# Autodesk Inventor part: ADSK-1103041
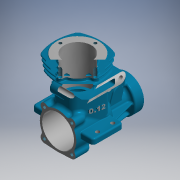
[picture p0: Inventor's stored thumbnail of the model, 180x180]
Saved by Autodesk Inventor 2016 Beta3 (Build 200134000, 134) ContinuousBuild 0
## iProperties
Shininess: 11.0
Length Units: 11269
Angle Units: 11279
Time Units: 11290
Mass Units: 11286
Length Display Precision: 2
Angle Display Precision: 2
Compacted: True
Created: 2000-07
Part Number: ADSK-1103041
Document SubType Name: Modeling
Material: Cast Steel
Description: ENGINE CASE - SIDE
Mass: 109.721 g
Surface Area: 158.984 cm^2
Volume: 13.9772 cm^3
Density: 7.85 g/cm^3
Appearance: Sky Blue Dark
Density: 0.0
Volumn: 0.0
Area: 0.0
PropertySet Name: Model Information
Control State: 0
Master: False
Checked Out: False
Author: Autodesk, Inc.
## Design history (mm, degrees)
node "Extrusion1" dims "d2" = 3.5, "d3" = 0
  sketch "Sketch2"
    geometry: L1 (-28.715, -16.977)-(11.285, -16.977); L2 (11.285, -16.977)-(11.285, 3.023); L3 (11.285, 3.023)-(-28.715, 3.023); L4 (-28.715, 3.023)-(-28.715, -16.977)
    constraints: 8 end point, 2 parallel, 1 horizontal, 1 perpendicular
    dimensions: "d0" = 40 distance of L2.end L3.end; "d1" = 20 distance of L3.end L1.start
workplane "Work Plane1"
workplane "Work Plane2"
node "Extrusion2" dims "d6" = 3.5, "d7" = 0
  sketch "Sketch3"
    geometry: L1 (20, -16.8)-(20, 16.8) reference; L2 (0, 0)-(40, 0) reference; C1 r 12 at (20, 0)
    constraints: 1 centre point, 1 midpoint
    dimensions: "d5" = 24 diameter of C1
node "Extrusion3" dims "d13" = 25, "d14" = 0
  sketch "Sketch4"
    geometry: L1 (-20.715, 3.023)-(3.285, 3.023); L2 (-2.715, -16.977)-(-14.715, -16.977); L3 (-8.715, -21.506)-(-8.715, 7.111) reference; L4 (-28.715, -16.977)-(-20.715, -16.977) reference; A1 r 36.333 centre (-33.049, 3.023) between (-2.715, -16.977) and (3.285, 3.023); A2 r 36.333 centre (15.618, 3.023) between (-20.715, 3.023) and (-14.715, -16.977)
    constraints: 4 end point, 4 point on circle, 2 centre point, 2 point on line, 1 collinear, 1 horizontal
    dimensions: "d8" = 24 distance of L1.start L1.end; "d9" = 12 distance of L2.start L2.end; "d10" = 6 distance from line of L3 L2.start (= 0.5 x d9); "d11" = 12 distance from line of L1.end L3 (= 0.5 x d8); "d12" = 20 distance between parallel lines of L2 L1
node "Extrusion4" dims "d15" = 2.5, "d16" = -15 deg
  sketch "Sketch5"
    geometry: A1 r 12 centre (-20, 3.5) between (-8, 3.5) and (-32, 3.5) reference; 1 further point
    constraints: 1 coincident, 1 horizontal alignment, 2 other
node "Extrusion5" dims "d18" = 14, "d19" = 0
  sketch "Sketch6"
    geometry: C1 r 11.33 at (0, 0) reference; C2 r 7.5 at (0, 0)
    constraints: 1 centre point, 1 coincident
    dimensions: "d17" = 15 diameter of C2
node "Extrusion6" dims "d21" = 6, "d22" = 0
  sketch "Sketch7"
    geometry: C1 r 7.5 at (0, 0) reference; C2 r 11 at (0, 0)
    constraints: 1 centre point, 1 coincident
    dimensions: "d20" = 22 diameter of C2
node "Extrusion7" dims "d24" = 1, "d25" = 0
  sketch "Sketch9"
    geometry: L1 (20.715, 3.023)-(28.715, 3.023) reference; L2 (20.715, 3.023)-(8.217, 3.023); L3 (8.217, 3.023)-(8.217, 19.523); L4 (8.217, 19.523)-(19.715, 19.523); L5 (18.215, 19.523)-(22.637, 3.023); L6 (19.715, 19.523)-(19.715, 25.523) reference; L7 (20.715, 3.023)-(20.045, 5.523) reference
    constraints: 8 end point, 2 parallel, 2 point on line, 1 collinear, 1 perpendicular
    dimensions: "d23" = 1.5 distance from line of L5.start L6
node "Mirror1"
node "Revolution1" dims "d28" = 90 deg
  sketch "Sketch10"
    geometry: L1 (-20, -3.5)-(0, -3.5) reference; L2 (-21.176, 0.363)-(-25.964, 13.518); L3 (-22.5, -2.5)-(-22.5, 7.83) reference; L4 (-22.5, 4)-(-36.5, 4) reference; L5 (-25.964, 13.518)-(-32.307, 11.21); L6 (-42.5, -14.5)-(-42.5, 7.5) reference; L7 (-32.307, 11.21)-(-27.519, -1.946); L8 (-27.519, -1.946)-(-21.176, 0.363)
    constraints: 8 end point, 2 perpendicular, 2 point on line, 1 parallel
    dimensions: "d26" = 70 deg angle of L1 L2; "d27" = 13.5 diameter of L2 L7; "d231" = 14 distance of L2.start L2.end
node "Extrusion9" dims "d35" = 1, "d36" = 0
  sketch "Sketch12"
    geometry: L1 (-26.964, 12.518)-(-19, 12.518); L2 (-19, 12.518)-(-19, 3); L3 (-19, 3)-(-26.964, 3); L4 (-26.964, 3)-(-26.964, 12.518); L5 (-25.964, 13.518)-(-22.5, 4) reference; L6 (-22.5, -2.5)-(-22.5, 7.83) reference; L7 (-20, 0)-(-20, 25) reference
    constraints: 8 end point, 2 parallel, 1 horizontal, 1 perpendicular
    dimensions: "d31" = 1 distance between parallel lines of L7 L2; "d32" = 1 distance from line of L5.start L4; "d33" = 1 distance from line of L5.end L3; "d34" = 1 horizontal distance of L5.start L1.start
workplane "Work Plane3"
  workaxis "Work Axis1"
node "Extrusion10" dims "d40" = 1, "d41" = 0
  sketch "Sketch13"
    geometry: L1 (-23, -12)-(-25.5, -11.33) reference; L2 (-25.5, -11.33)-(-25.5, 8.012) reference; L3 (-39.5, -11)-(-39.5, 11) reference; L4 (-25.5, -7.5)-(-39.5, -7.5) reference; L5 (-23, -12)-(-39.5, -10); L6 (-39.5, -6.5)-(-23, -6.5); L7 (-23, -6.5)-(-23, -12); 3 further points
    constraints: 6 end point, 2 point on line, 1 parallel, 1 perpendicular
    dimensions: "d38" = 1 distance of L3.start L5.end; "d39" = 1 distance between parallel lines of L4 L6
node "Circular Pattern1" dims "d42" = 30, "d44" = 45 deg
workaxis "Work Axis2"
workplane "Work Plane4"
workplane "Work Plane5"
workpoint "Work Point1"
node "Extrusion11" dims "d47" = 1, "d48" = 0
  sketch "Sketch14"
    geometry: L1 (2.217, 13.646)-(2.581, 12.646) reference; L2 (-3.407, -0.873)-(4.042, -0.873); L3 (-13.419, 36.867)-(12.256, -33.673) reference; L4 (4.042, -0.873)-(1.423, 6.324); L5 (-5.155, 3.93)-(-3.407, -0.873); A1 r 3.5 centre (-1.866, 5.127) between (1.423, 6.324) and (-5.155, 3.93); 1 further point
    constraints: 6 end point, 2 parallel, 2 point on circle, 2 tangent, 1 centre point, 1 horizontal, 1 point on line
    dimensions: "d45" = 3.5 radius of A1; "d46" = 6 distance from line of A1.centre L2; "d232" = 1 distance from line of point (5.681, 0.127) L2
node "Extrusion12" dims "d54" = 8, "d55" = 0
  sketch "Sketch15"
    geometry: L1 (-9, 9)-(9, 9); L2 (9, 9)-(9, -9); L3 (9, -9)-(-9, -9); L4 (-9, -9)-(-9, 9); C1 r 12 at (0, 0) reference; C2 r 2.5 at (-9, 9); C3 r 2.5 at (9, 9); C4 r 2.5 at (9, -9); C5 r 2.5 at (-9, -9)
    constraints: 8 end point, 4 centre point, 4 coincident, 3 equal radius, 2 parallel, 2 perpendicular, 1 horizontal
    dimensions: "d50" = 18 distance of L2.end L3.end; "d51" = 9 distance from line of C1.centre L4 (= 0.5 x d50); "d52" = 9 distance from line of C1.centre L3 (= d51); "d53" = 5 diameter of C3
node "Extrusion13" dims "d56" = 8, "d57" = 0
  sketch "Sketch16"
    geometry: L1 (10.857, -11.496)-(19.314, -11.98); L2 (29.143, -11.496)-(20.686, -11.98); A1 r 2.5 centre (11, -9) between (10.039, -6.692) and (13.308, -9.961) reference; A2 r 12 centre (20, 0) between (13.308, -9.961) and (26.692, -9.961) reference; A3 r 2.5 centre (29, -9) between (26.692, -9.961) and (29.961, -6.692) reference
    constraints: 4 end point, 4 point on circle, 4 tangent
node "Fillet1" dims "d58" = 2.5
node "Fillet2" dims "d59" = 2
node "Fillet3" dims "d60" = 5
node "Fillet4" dims "d61" = 3
node "Fillet5" dims "d62" = 2
node "Revolution2" dims "d63" = 180 deg
  sketch "Sketch17"
    geometry: L1 (0.686, 11.98)-(9.143, 11.496) reference; L2 (9.143, 11.496)-(0.686, 11.98); L3 (0.686, 11.98)-(0.543, 9.484); L4 (0.543, 9.484)-(9, 9); L5 (9, 9)-(9.143, 11.496); L6 (9, 9)-(11.496, 8.857); A1 r 12 centre (0, 0) between (9.961, 6.692) and (0.686, 11.98) reference; A2 r 2.5 centre (9, 9) between (9.961, 6.692) and (9.143, 11.496) reference
    constraints: 10 end point, 3 equal length, 2 perpendicular, 2 tangent, 1 point on circle, 1 point on line
node "Mirror2"
node "Fillet6" dims "d64" = 2.5
node "Fillet7" dims "d65" = 2
node "Fillet8" dims "d66" = 3.5
node "Fillet9" dims "d67" = 2
node "Fillet10" dims "d68" = 1
node "Fillet11" dims "d69" = 1
node "Fillet12" dims "d70" = 0.5
node "Fillet13" dims "d71" = 0.45
node "Fillet15" dims "d73" = 1
node "Fillet16" dims "d74" = 0.5
node "Fillet17" dims "d75" = 2
node "Fillet18" dims "d76" = 1
node "Fillet19" dims "d77" = 0.5
node "Fillet20" dims "d78" = 0.5
node "Fillet21" dims "d79" = 1
node "Fillet22" dims "d80" = 0.5
node "Fillet23" dims "d81" = 0.5
node "Fillet24" dims "d82" = 1
node "Fillet25" dims "d83" = 0.5
node "Extrusion14" dims "d84" = 9, "d85" = 0
  sketch "Sketch18"
    geometry: L1 (-17.028, 3.023)-(-0.402, 3.023) reference; L2 (-8.715, -24.577)-(-8.715, 7.623) reference; C1 r 10.018 at (-8.715, -6.996); A1 r 36.333 centre (15.618, 3.023) between (-20.508, -0.85) and (-16.281, -14.371) reference
    constraints: 2 tangent, 1 centre point, 1 point on line
node "Extrusion15" dims "d90" = 1, "d91" = 0
  sketch "Sketch19"
    geometry: L1 (5.035, 6.754)-(-22.465, 6.754); L2 (-22.465, 6.754)-(-22.465, -20.746); L3 (-22.465, -20.746)-(5.035, -20.746); L4 (5.035, -20.746)-(5.035, 6.754); A1 r 10.018 centre (-8.715, -6.996) between (0.549, -10.81) and (-8.715, 3.023) reference; A2 r 27.5 centre (-22.465, -6.996) between (2.599, -18.31) and (2.599, 4.319); A3 r 27.5 centre (5.035, -6.996) between (-20.03, 4.319) and (-20.03, -18.31); A4 r 27.5 centre (-8.715, 6.754) between (-20.03, -18.31) and (2.599, -18.31); A5 r 27.5 centre (-8.715, -20.746) between (2.599, 4.319) and (-20.03, 4.319); A6 r 29.032 centre (-8.715, -20.746) between (-22.465, 4.823) and (-23.458, 4.264)
    constraints: 12 point on circle, 8 end point, 5 centre point, 3 midpoint, 3 tangent, 2 parallel, 2 perpendicular, 1 horizontal, 1 point on line
    dimensions: "d86" = 27.5 distance of L2.end L3.end; "d87" = 13.75 distance from line of L4 A1.centre (= 0.5 x d86); "d88" = 13.75 distance from line of L3 A1.centre (= d87); "d89" = 13.75 distance from line of L2 A4.centre (= d87)
node "Fillet26" dims "d92" = 2
workplane "Work Plane6"
node "Extrusion16" dims "d95" = 1, "d96" = 0
  sketch "Sketch20"
    geometry: A1 r 27.5 centre (-8.715, -20.746) between (1.847, 4.645) and (-19.278, 4.645) reference; A2 r 27.5 centre (5.035, -6.996) between (-20.356, 3.567) and (-20.356, -17.558) reference; A3 r 2 centre (-18.509, 2.798) between (-19.278, 4.645) and (-20.356, 3.567) reference; A4 r 2 centre (1.079, 2.798) between (2.925, 3.567) and (1.847, 4.645) reference; A5 r 27.5 centre (-22.465, -6.996) between (2.925, -17.558) and (2.925, 3.567) reference; A6 r 2 centre (1.079, -16.79) between (1.847, -18.636) and (2.925, -17.558) reference; A7 r 27.5 centre (-8.715, 6.754) between (-19.278, -18.636) and (1.847, -18.636) reference; A8 r 2 centre (-18.509, -16.79) between (-20.356, -17.558) and (-19.278, -18.636) reference; A9 r 28 centre (-8.715, -20.746) between (2.039, 5.107) and (-19.47, 5.107); A10 r 2.5 centre (1.079, 2.798) between (3.387, 3.759) and (2.039, 5.107); A11 r 28 centre (-22.465, -6.996) between (3.387, -17.75) and (3.387, 3.759); A12 r 2.5 centre (1.079, -16.79) between (2.039, -19.098) and (3.387, -17.75); A13 r 28 centre (-8.715, 6.754) between (-19.47, -19.098) and (2.039, -19.098); A14 r 2.5 centre (-18.509, -16.79) between (-20.818, -17.75) and (-19.47, -19.098); A15 r 28 centre (5.035, -6.996) between (-20.818, 3.759) and (-20.818, -17.75); A16 r 2.5 centre (-18.509, 2.798) between (-19.47, 5.107) and (-20.818, 3.759)
    constraints: 16 point on circle, 8 centre point, 7 other
    dimensions: "d94" = 0.5 radial gap between concentric circles of A9 A1
workplane "Work Plane7"
node "Extrusion17" dims "d99" = 1, "d100" = 0
  sketch "Sketch21"
    geometry: A1 r 28 centre (-8.715, -20.746) between (2.039, 5.107) and (-19.47, 5.107) reference; A2 r 28 centre (5.035, -6.996) between (-20.818, 3.759) and (-20.818, -17.75) reference; A3 r 2.5 centre (-18.509, -16.79) between (-20.818, -17.75) and (-19.47, -19.098) reference; A4 r 2.5 centre (-18.509, 2.798) between (-19.47, 5.107) and (-20.818, 3.759) reference; A5 r 28 centre (-8.715, 6.754) between (-19.47, -19.098) and (2.039, -19.098) reference; A6 r 2.5 centre (1.079, -16.79) between (2.039, -19.098) and (3.387, -17.75) reference; A7 r 28 centre (-22.465, -6.996) between (3.387, -17.75) and (3.387, 3.759) reference; A8 r 2.5 centre (1.079, 2.798) between (3.387, 3.759) and (2.039, 5.107) reference; A9 r 28.5 centre (-8.715, -20.746) between (2.231, 5.568) and (-19.662, 5.568); A10 r 3 centre (1.079, 2.798) between (3.849, 3.951) and (2.231, 5.568); A11 r 28.5 centre (-22.465, -6.996) between (3.849, -17.942) and (3.849, 3.951); A12 r 3 centre (1.079, -16.79) between (2.231, -19.56) and (3.849, -17.942); A13 r 28.5 centre (-8.715, 6.754) between (-19.662, -19.56) and (2.231, -19.56); A14 r 3 centre (-18.509, -16.79) between (-21.279, -17.942) and (-19.662, -19.56); A15 r 28.5 centre (5.035, -6.996) between (-21.279, 3.951) and (-21.279, -17.942); A16 r 3 centre (-18.509, 2.798) between (-19.662, 5.568) and (-21.279, 3.951)
    constraints: 16 point on circle, 8 centre point, 7 other
    dimensions: "d98" = 0.5 radial gap between concentric circles of A9 A1
workplane "Work Plane8"
node "Extrusion18" dims "d103" = 1, "d104" = 0
  sketch "Sketch22"
    geometry: A1 r 28.5 centre (-8.715, -20.746) between (2.231, 5.568) and (-19.662, 5.568) reference; A2 r 3 centre (-18.509, 2.798) between (-19.662, 5.568) and (-21.279, 3.951) reference; A3 r 28.5 centre (5.035, -6.996) between (-21.279, 3.951) and (-21.279, -17.942) reference; A4 r 3 centre (-18.509, -16.79) between (-21.279, -17.942) and (-19.662, -19.56) reference; A5 r 28.5 centre (-8.715, 6.754) between (-19.662, -19.56) and (2.231, -19.56) reference; A6 r 3 centre (1.079, -16.79) between (2.231, -19.56) and (3.849, -17.942) reference; A7 r 28.5 centre (-22.465, -6.996) between (3.849, -17.942) and (3.849, 3.951) reference; A8 r 3 centre (1.079, 2.798) between (3.849, 3.951) and (2.231, 5.568) reference; A9 r 29 centre (-8.715, -20.746) between (2.423, 6.03) and (-19.854, 6.03); A10 r 3.5 centre (1.079, 2.798) between (4.31, 4.143) and (2.423, 6.03); A11 r 29 centre (-22.465, -6.996) between (4.31, -18.134) and (4.31, 4.143); A12 r 3.5 centre (1.079, -16.79) between (2.423, -20.021) and (4.31, -18.134); A13 r 29 centre (-8.715, 6.754) between (-19.854, -20.021) and (2.423, -20.021); A14 r 3.5 centre (-18.509, -16.79) between (-21.741, -18.134) and (-19.854, -20.021); A15 r 29 centre (5.035, -6.996) between (-21.741, 4.143) and (-21.741, -18.134); A16 r 3.5 centre (-18.509, 2.798) between (-19.854, 6.03) and (-21.741, 4.143)
    constraints: 16 point on circle, 8 centre point, 7 other
    dimensions: "d102" = 0.5 radial gap between concentric circles of A9 A1
node "Extrusion19" dims "d108" = 1, "d109" = 0
  sketch "Sketch23" dims "d105" = 23
    geometry: L1 (-8.715, -31.799)-(-8.715, 35.076) reference; C1 r 10.018 at (-8.715, -6.996) reference; A1 r 2 centre (-8.715, 4.504) between (-6.717, 4.422) and (-10.714, 4.422); A2 r 2 centre (-4.719, 4.339) between (-6.717, 4.422) and (-5.384, 2.453); A3 r 2 centre (-12.712, 4.339) between (-12.047, 2.453) and (-10.714, 4.422); A4 r 10.018 centre (-8.715, -6.996) between (-5.384, 2.453) and (-12.047, 2.453); 1 further point
    constraints: 8 point on circle, 4 centre point, 4 tangent, 2 equal radius, 1 coincident, 1 concentric, 1 point on line, 1 vertical alignment, 2 other
    dimensions: "d106" = 4 diameter of A1; "d107" = 2 radius of A2
workaxis "Work Axis3"
node "Circular Pattern2" dims "d110" = 40, "d112" = 360 deg
node "Fillet27" dims "d113" = 0.5
node "Fillet28" dims "d114" = 0.5
workplane "Work Plane9"
workaxis "Work Axis4"
  workpoint "Work Point2"
  workpoint "Work Point3"
node "Extrusion20" dims "d119" = 17.5, "d120" = 0
  sketch "Sketch24"
    geometry: L1 (16.322, 24.5)-(-52.304, 24.5) reference; L2 (-9.982, -25.58)-(-9.982, 43.93) reference; L3 (3.018, 17.5)-(-22.982, 17.5); L4 (-22.982, 24.5)-(3.018, 24.5); A1 r 3.5 centre (-22.982, 21) between (-22.982, 24.5) and (-22.982, 17.5); A2 r 3.5 centre (3.018, 21) between (3.018, 17.5) and (3.018, 24.5)
    constraints: 4 end point, 4 point on circle, 4 tangent, 2 centre point, 1 collinear, 1 parallel, 1 perpendicular
    dimensions: "d116" = 26 distance of A1.centre A2.centre; "d117" = 13 distance from line of L2 A2.centre (= 0.5 x d116); "d118" = 3.5 radius of A1
node "Fillet29" dims "d121" = 0.5
node "Fillet30" dims "d122" = 1
node "Extrusion21" dims "d123" = 18, "d124" = 0
  sketch "Sketch25"
    geometry: L1 (24, 0)-(24, -2.921) reference; L2 (24, -1.216)-(24, -4.821); A1 r 3.5 centre (21, -3.018) between (17.5, -3.018) and (24.351, -4.028) reference; A2 r 3.5 centre (21, -3.018) between (24, -1.216) and (24, -4.821)
    constraints: 4 point on circle, 2 end point, 1 centre point, 1 coincident, 1 collinear, 1 point on line
node "Fillet31" dims "d125" = 2.5
node "Extrusion22" dims "d126" = 18, "d127" = 0
  sketch "Sketch26"
    geometry: L1 (24, 22.884)-(24, 20) reference; L2 (24, 21.179)-(24, 24.784); A1 r 2.5 centre (21, 22.982) between (23.394, 23.703) and (18.5, 22.982) reference; A2 r 3.5 centre (21, 22.982) between (24, 24.784) and (24, 21.179); A3 r 3.5 centre (21, 22.982) between (24.351, 23.991) and (17.5, 22.982) reference
    constraints: 2 end point, 2 point on circle, 1 centre point, 1 coincident, 1 collinear, 1 concentric, 1 point on line
node "Fillet32" dims "d128" = 2.5
node "Fillet33" dims "d129" = 0.5
node "Fillet34" dims "d130" = 0.45
node "Extrusion23" dims "d134" = 18, "d135" = 0
  sketch "Sketch27"
    geometry: L1 (12.518, 25.62)-(12.518, 20) reference; L2 (18.56, 20)-(6.19, 20) reference; L3 (17.5, 22.982)-(17.5, -3.018) reference; L4 (17.5, 21)-(12.518, 22.81); L5 (17.5, 21)-(17.5, 19); L6 (12.518, 19)-(17.5, 19); L7 (12.518, 19)-(12.518, 22.81)
    constraints: 8 end point, 2 point on line, 1 collinear, 1 midpoint, 1 perpendicular
    dimensions: "d131" = 1 distance from line of L2 L4.start; "d132" = 2.8101 distance of L1.start L4.end (derived); "d133" = 2 distance from line of L4.start L6
node "Fillet35" dims "d136" = 1
node "Fillet36" dims "d137" = 0.5
node "Fillet37" dims "d138" = 0.5
node "Hole1" dims "d139" = 2.013, "d140" = 4, "d141" = 2, "d142" = 60 deg, "d143" = 5, "d144" = 118 deg
  sketch "Sketch28"
    geometry: A1 r 2.5 centre (29, 9) between (30.967, 7.457) and (27.457, 10.967) reference; A2 r 2.5 centre (11, 9) between (12.543, 10.967) and (9.033, 7.457) reference; A3 r 2.5 centre (11, -9) between (8.939, -7.585) and (10.857, -11.496) reference; A4 r 2.5 centre (29, -9) between (29.143, -11.496) and (31.061, -7.585) reference
node "Hole2" dims "d145" = 3, "d146" = 4, "d147" = 2, "d148" = 60 deg, "d149" = 5, "d150" = 118 deg
  sketch "Sketch29"
    geometry: A1 r 2.5 centre (21, 22.982) between (23.394, 23.703) and (18.5, 22.982) reference; A2 r 2.5 centre (21, -3.018) between (18.5, -3.018) and (23.394, -3.739) reference
node "Extrusion24" dims "d152" = 25, "d153" = 0
  sketch "Sketch30"
    geometry: C1 r 9 at (-8.715, -6.996); A1 r 10.518 centre (-8.715, -6.996) between (-18.635, -10.493) and (-12.213, -16.915) reference
    constraints: 1 centre point, 1 coincident
    dimensions: "d151" = 18 diameter of C1
node "Extrusion25" dims "d154" = 0.25, "d155" = 0
  sketch "Sketch31"
    geometry: C1 r 9 at (-8.715, -6.996) reference; A1 r 28.5 centre (-8.715, 6.754) between (-19.662, -19.56) and (2.231, -19.56) reference; 1 further point
    constraints: 1 coincident, 1 vertical alignment, 2 other
node "Fillet38" dims "d156" = 0.5
node "Hole3" dims "d157" = 2.013, "d158" = 4, "d159" = 2, "d160" = 60 deg, "d161" = 8, "d162" = 118 deg, "d260" = 6
  sketch "Sketch32"
    geometry: A1 r 2.5 centre (-8.715, 4.504) between (-6.218, 4.401) and (-11.213, 4.401) reference; 2 further points
node "Circular Pattern3" dims "d163" = 40, "d165" = 360 deg
workplane "Work Plane10"
node "Extrusion26" dims "d172" = 1, "d173" = 0
  sketch "Sketch33"
    geometry: L1 (17.028, 3.023)-(11.715, 3.023) reference; L2 (20.526, -0.601)-(20.118, -12.124); L3 (18.88, -14.446)-(13.843, -16.581); L4 (15.654, -15.27)-(18.9, -13.894); A1 r 36.333 centre (-15.618, 3.023) between (16.281, -14.371) and (20.508, -0.85) reference; A2 r 3.5 centre (17.028, -0.477) between (20.508, -0.85) and (17.028, 3.023) reference; A3 r 5 centre (11.892, -11.977) between (11.892, -16.977) and (16.281, -14.371) reference; A4 r 2 centre (18.119, -12.053) between (18.9, -13.894) and (20.118, -12.124)
    constraints: 6 end point, 5 point on circle, 4 tangent, 1 centre point, 1 parallel
    dimensions: "d168" = 115 deg angle of L3 L2; "d169" = 87.9716 deg angle of L2 L1; "d170" = 2 radius of A4; "d171" = 0.5 distance between parallel lines of L3 L4
node "Fillet39" dims "d174" = 0.5
node "Fillet40" dims "d175" = 0.5
node "Rectangular Pattern1" dims "d176" = 40, "d178" = 3
node "Extrusion27" dims "d180" = 4, "d181" = 0
  sketch "Sketch34"
    geometry: C1 r 11 at (0, 0) reference; C2 r 8 at (0, 0)
    constraints: 1 centre point, 1 coincident
    dimensions: "d179" = 16 diameter of C2
node "Extrusion28" dims "d183" = 4, "d184" = 0
  sketch "Sketch35"
    geometry: C1 r 8 at (0, 0) reference; C2 r 6 at (0, 0)
    constraints: 1 centre point, 1 coincident
    dimensions: "d182" = 12 diameter of C2
node "Extrusion29" dims "d186" = 20, "d187" = 0
  sketch "Sketch36"
    geometry: C1 r 10.5 at (20, 0); A1 r 12 centre (20, 0) between (30.859, -5.106) and (30.749, 5.334) reference
    constraints: 1 centre point, 1 coincident
    dimensions: "d185" = 21 diameter of C1
node "Extrusion30" dims "d189" = 22, "d190" = 0
  sketch "Sketch37"
    geometry: C1 r 7 at (-8.715, -6.996); A1 r 13.75 centre (-8.715, -6.996) between (5.035, -6.996) and (-22.465, -6.996) reference
    constraints: 1 centre point, 1 coincident
    dimensions: "d188" = 14 diameter of C1
node "Extrusion31" dims "d192" = 5, "d193" = 0
  sketch "Sketch38"
    geometry: C1 r 10.5 at (0, 0) reference; C2 r 9.5 at (0, 0)
    constraints: 1 centre point, 1 coincident
    dimensions: "d191" = 19 diameter of C2
node "Extrusion32" dims "d201" = 16.5, "d202" = 0
  sketch "Sketch41"
    geometry: L1 (-17.5, 22.982)-(-17.5, -3.018) reference; L2 (-24.5, -3.018)-(-24.5, 22.982) reference; L3 (-23, 10.982)-(-19, 10.982); L4 (-19, 10.982)-(-19, -0.518); L5 (-19, -0.518)-(-23, -0.518); L6 (-23, -0.518)-(-23, 10.982); L7 (-34.25, 18.982)-(-9, 18.982) reference; L8 (-34.25, 0.982)-(-9, 0.982) reference; C1 r 1.5 at (-21, -3.018) reference
    constraints: 8 end point, 2 parallel, 1 horizontal, 1 perpendicular
    dimensions: "d199" = 1.5 distance between parallel lines of L2 L6; "d200" = 1.5 distance between parallel lines of L1 L4 (= d199); "d204" = 2.5 distance from line of L5 C1.centre; "d205" = 8 distance between parallel lines of L7 L3
node "Fillet42" dims "d206" = 1.63
node "Fillet41" dims "d203" = 1
node "Extrusion33" dims "d210" = 4, "d211" = 0
  sketch "Sketch42"
    geometry: L1 (6.056, -10.5)-(-8.814, -10.5) reference; L2 (6.056, 0)-(0, 0) reference; L3 (6.056, -17.5)-(-10.444, -17.5) reference; L4 (6.056, 15.5)-(-10.444, 15.5) reference; L5 (5.239, -17.5)-(-10.444, -17.5); L6 (-4.472, 8.5)-(6.056, 8.5); L7 (6.056, 0)-(6.056, 8.5); C1 r 9 at (-8.944, -1) reference; A1 r 10.5 centre (-8.944, -1) between (1.508, 0) and (-4.472, 8.5); 3 further points
    constraints: 7 end point, 4 coincident, 2 parallel, 2 point on circle, 2 point on line, 1 centre point, 1 perpendicular
    dimensions: "d207" = 7 distance between parallel lines of L5 L1 (derived); "d208" = 7 distance between parallel lines of L4 L6 (derived); "d209" = 1.5 radial gap between concentric circles of A1 C1
node "Fillet43" dims "d212" = 3
node "Fillet44" dims "d213" = 1
node "Fillet45" dims "d214" = 2
node "Fillet46" dims "d215" = 0.5
workplane "Work Plane13"
node "Extrusion34" dims "d219" = 13, "d220" = 0
  sketch "Sketch43"
    geometry: L1 (-10.366, 28.481)-(15.384, -42.268) reference; L2 (0.134, -0.368)-(6.712, 2.026); L3 (-7.406, 0.612)-(6.343, 2.309) reference; C1 r 2.75 at (6.712, 2.026); 1 further point
    constraints: 2 end point, 1 centre point, 1 coincident, 1 perpendicular, 1 point on line
    dimensions: "d216" = 7 distance of L2.start L2.end; "d217" = 3.5 distance between parallel lines of L2 L3; "d218" = 5.5 diameter of C1
node "Fillet47" dims "d221" = 0.5
node "Extrusion35" dims "d223" = 15, "d224" = 0
  sketch "Sketch44"
    geometry: C1 r 5.5 at (6.75, 7); A1 r 6.75 centre (6.75, 7) between (6.75, 0.25) and (6.75, 0.25) reference; A2 r 6.75 centre (6.75, 7) between (6.75, 0.25) and (6.75, 0.25) reference
    constraints: 1 centre point, 1 coincident
    dimensions: "d222" = 11 diameter of C1
node "Extrusion36" dims "d226" = 15, "d227" = 0
  sketch "Sketch45"
    geometry: C1 r 2.75 at (0, 0) reference; C2 r 2 at (0, 0)
    constraints: 1 centre point, 1 coincident
    dimensions: "d225" = 4 diameter of C2
node "Hole4" dims "d233" = 2.5, "d234" = 4, "d235" = 2, "d236" = 60 deg, "d237" = 8, "d238" = 118 deg
  sketch "Sketch46"
    geometry: C1 r 1.078 at (8.285, -11.027) reference; C2 r 1.078 at (8.285, -1.027) reference; C3 r 1.078 at (-25.715, -1.977) reference; C4 r 1.078 at (-25.715, -11.977) reference
fillet "Fillet48" dims "d240" = 1
fillet "Fillet49" dims "d241" = 1
fillet "Fillet51" dims "d243" = 0.5
sketch "Sketch49"
  geometry: L1 (6.9, 8.859)-(16.548, 8.859); L2 (16.548, 8.859)-(16.548, 5.238); L3 (16.548, 5.238)-(6.9, 5.238); L4 (6.9, 5.238)-(6.9, 8.859)
  constraints: 2 other
emboss "Emboss2" sketch "Sketch49" dims "d248" = 0.5, "d249" = 0
workplane "Work Plane14"
workplane "Work Plane15"
  workaxis "Work Axis5"
  workaxis "Work Axis6"
body "Solid1"
other parameters: "d4" = 3, "d37" = 45 deg, "d93" = 2, "d97" = 2, "d101" = 2, "d115" = -15, "d166" = 2, "d259" = 0, "d261" = 0
